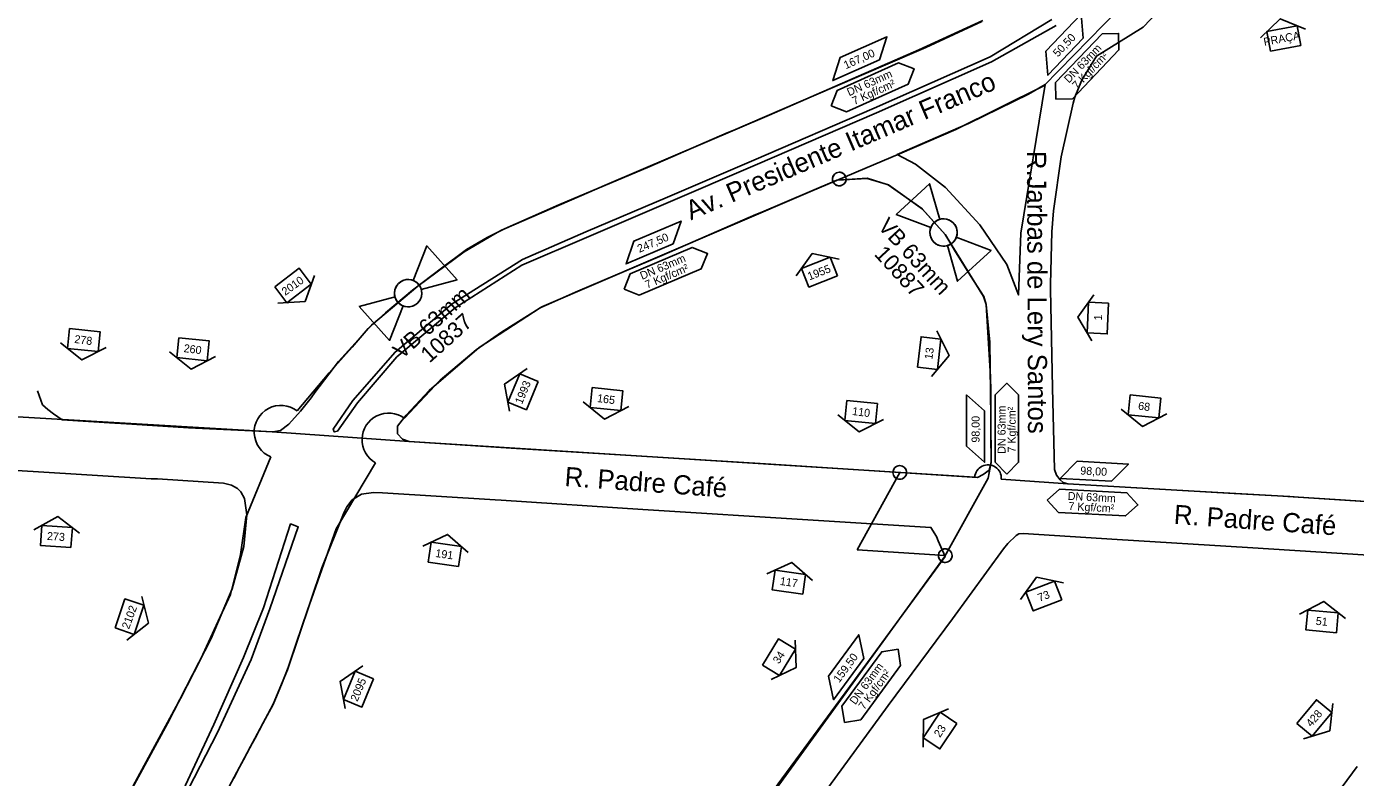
# Model space of a CAD drawing. Extents: x 656692 to 673945, y 7585994 to 7599066.
# Drawn here: x 669220.6 to 669718.8, y 7591557.3 to 7591838.6 of the extents above; entities that cross this region are included whole.
import ezdxf

# ---------------------------------------------------------------- set-up
doc = ezdxf.new("R2010")
doc.units = 0
for name, color, linetype in [('FORMATO', 7, 'Continuous'), ('LOGRADOURO', 7, 'Continuous'), ('LOGRADOURO_TEXTO', 7, 'Continuous'), ('NUM_REF', 7, 'Continuous'), ('SIMBOLO', 7, 'Continuous'), ('TEXTO', 7, 'Continuous'), ('TUBO_PEAD_GN_63', 7, 'Continuous'), ('VALVULA_PEAD_63', 7, 'Continuous')]:
    doc.layers.add(name, color=color, linetype=linetype)

# ---------------------------------------------------------------- blocks, each defined once
blk = doc.blocks.new('INTERLIGACAO_5')
at = {"layer": 'SIMBOLO'}
blk.add_circle((0, 0), 1.28, dxfattribs=at)
for start, end in [(0, 180), (180, 0)]:
    blk.add_arc((0, 0), 1.28, start, end, dxfattribs=at)
blk = doc.blocks.new('VALVULA_PEAD_DN_9')
at = {"layer": 'VALVULA_PEAD_63'}
for points in [[(-1.14, 0.57), (-4.25, 2.13), (-4.25, -2.13), (-1.14, -0.57)], [(-1.14, -0.57), (-4.25, -2.13), (-4.25, 2.13), (-1.14, 0.57)], [(1.14, -0.57), (4.25, -2.13), (4.25, 2.13), (1.14, 0.57)], [(1.14, -0.57), (4.25, -2.13), (4.25, 2.13), (1.14, 0.57)]]:
    blk.add_lwpolyline(points, dxfattribs=at)
blk.add_circle((0, 0), 1.28, dxfattribs=at)
for start, end in [(90, 270), (270, 90), (153.4349, 206.5651), (0, 26.5651), (333.4349, 0)]:
    blk.add_arc((0, 0), 1.28, start, end, dxfattribs=at)
blk = doc.blocks.new('NUM_REF_1')
at = {"layer": 'NUM_REF'}
blk.add_lwpolyline([(-4.3125, 0.9375), (0, 3.75), (4.3125, 0.9375)], dxfattribs=at)
blk.add_lwpolyline([(2.875, -1.875), (2.875, 1.875), (-2.875, 1.875), (-2.875, -1.875)], close=True, dxfattribs=at)

msp = doc.modelspace()

# ---------------------------------------------------------------- linework, layer by layer
at = {"layer": 'LOGRADOURO'}
for p, q in [((669557.74, 7591830.71), (669578.71, 7591840.55)), ((669522.92, 7591815.77), (669555.15, 7591829.59)), ((669555.15, 7591829.59), (669557.74, 7591830.71)), ((669485.55, 7591799.63), (669522.92, 7591815.77)), ((669483.29, 7591798.76), (669485.55, 7591799.63)), ((669454.29, 7591786.15), (669483.29, 7591798.76)), ((669420.18, 7591771.85), (669454.29, 7591786.15)), ((669398.71, 7591762.39), (669420.18, 7591771.85)), ((669384.69, 7591754.23), (669396.19, 7591760.99)), ((669396.19, 7591760.99), (669398.71, 7591762.39)), ((669367.29, 7591741.39), (669384.69, 7591754.23)), ((669349.95, 7591726.69), (669367.29, 7591741.39)), ((669337.5, 7591713.13), (669349.95, 7591726.69)), ((669328.6, 7591701.5), (669337.5, 7591713.13)), ((669224.67, 7591702.13), (669226.6, 7591696.86)), ((669327.32, 7591699.57), (669328.6, 7591701.5)), ((669226.6, 7591696.86), (669228.58, 7591695.12)), ((669228.58, 7591695.12), (669230.71, 7591693.48)), ((669323.29, 7591694.51), (669327.32, 7591699.57)), ((669230.71, 7591693.48), (669233.91, 7591691.22)), ((669233.91, 7591691.22), (669253.68, 7591690.02)), ((669253.68, 7591690.02), (669258, 7591689.71)), ((669258, 7591689.71), (669281.29, 7591688.32)), ((669315.77, 7591687.26), (669318.85, 7591689.69)), ((669318.85, 7591689.69), (669323.29, 7591694.51)), ((669281.29, 7591688.32), (669312.96, 7591686.77)), ((669312.96, 7591686.77), (669315.77, 7591687.26))]:
    msp.add_line(p, q, dxfattribs=at)
for points in [[(669732.22, 7591660.05), (669691.63, 7591662.69), (669689.59, 7591662.76), (669658.39, 7591664.55), (669611.03, 7591667.25), (669609.28, 7591667.76), (669608.08, 7591668.73), (669606.72, 7591670.57), (669605.94, 7591672.66), (669605.3, 7591703.26), (669604.55, 7591740.13), (669604.46, 7591742.15), (669604.98, 7591761.74), (669605.59, 7591769.54), (669608.47, 7591789.79), (669613, 7591809.88), (669613.68, 7591812.11), (669616.11, 7591818.23), (669616.74, 7591819.42), (669621.81, 7591827.55), (669639.28, 7591838.38), (669655.23, 7591855.29)], [(669337.11, 7591687.05), (669335.94, 7591686.75), (669335.53, 7591687.79), (669342.86, 7591698.48), (669358.73, 7591716.65), (669380.11, 7591734.71), (669406.54, 7591751.38), (669430.33, 7591761.73), (669460.86, 7591774.63), (669493.26, 7591788.52), (669538.4, 7591808), (669581.93, 7591827.22), (669604.97, 7591841.22)], [(669606.58, 7591839), (669582.43, 7591825.39), (669539.2, 7591806.27), (669493.71, 7591786.66), (669460.25, 7591772.34), (669431.34, 7591760), (669406.24, 7591749.17), (669381.25, 7591733.18), (669359.46, 7591714.81), (669344.65, 7591697.65), (669337.11, 7591687.05)], [(669547.01, 7591790.73), (669553.9, 7591787.09), (669565.19, 7591778.29), (669578.01, 7591764.38), (669588.19, 7591749.42), (669592.52, 7591738.06), (669593.32, 7591761.21), (669602.48, 7591816.85), (669596.27, 7591813.33), (669573.7, 7591802.28), (669547.01, 7591790.73)], [(669437.06, 7591678.51), (669402.31, 7591680.71), (669364.01, 7591683.16), (669361.5, 7591684.03), (669359.6, 7591686.08), (669359.65, 7591688.85), (669361.37, 7591691.19), (669362.95, 7591692.98), (669371.47, 7591702.22), (669390.3, 7591718.32), (669413.13, 7591733.19), (669415.36, 7591734.21), (669427.32, 7591739.5), (669458.79, 7591752.86), (669494.03, 7591768.15), (669496.29, 7591769.05), (669524.33, 7591781.05), (669535.81, 7591781.75), (669543.63, 7591779.34), (669556.22, 7591770.45), (669564.95, 7591760.73), (669579.43, 7591737.44), (669580.34, 7591734.53), (669581.78, 7591720.39), (669582.18, 7591692.15), (669582.26, 7591675.32), (669581.49, 7591672.43), (669579.2, 7591670.76), (669577.19, 7591669.72), (669497.67, 7591674.79), (669437.06, 7591678.51)], [(669189.53, 7591673.97), (669223.09, 7591671.85), (669267.28, 7591669.21), (669269.69, 7591669.12), (669294.37, 7591667.49), (669297.43, 7591666.85), (669299.71, 7591665.59), (669300.96, 7591664.35), (669302.29, 7591661.82), (669303.15, 7591655.69), (669302.03, 7591643.79), (669297.61, 7591627.93), (669289.8, 7591609.29), (669273.43, 7591577.49), (669247.84, 7591530.44), (669246.69, 7591528.11), (669221.83, 7591481.25), (669219.83, 7591477.69)], [(669487.41, 7591534.49), (669505.53, 7591559.16), (669537.66, 7591602.72), (669564.95, 7591640.08), (669562.43, 7591645.95), (669561.78, 7591647.57), (669559.65, 7591650.99), (669515.56, 7591653.71), (669451.69, 7591657.68), (669398.48, 7591661.15), (669396.27, 7591661.26), (669354.04, 7591663.91), (669350.67, 7591664.04), (669346.21, 7591663.4), (669342.65, 7591661.24), (669340.62, 7591658.69), (669339.71, 7591656.73), (669331.27, 7591635.86), (669318.45, 7591597.66), (669313, 7591584.7), (669288.66, 7591539.12)], [(669237.18, 7591472.91), (669238.3, 7591472.4), (669256.41, 7591505.89), (669276.89, 7591544.54), (669292.15, 7591574.14), (669304.82, 7591601.5), (669311.85, 7591620.43), (669322.45, 7591651.2), (669319.55, 7591652.25), (669309.38, 7591620.83), (669301.89, 7591602.24), (669290.79, 7591577.08), (669275.65, 7591544.75), (669254.37, 7591505.12), (669237.18, 7591472.91)], [(669516.49, 7591547.19), (669543.69, 7591584.23), (669567.75, 7591616.76), (669586.85, 7591643), (669588.45, 7591644.89), (669591.69, 7591647.93), (669592.62, 7591648.55), (669594.2, 7591648.66), (669629.53, 7591646.44), (669678.34, 7591643.5), (669731.61, 7591640.12)], [(669719.43, 7591561.36), (669709.96, 7591548.49)]]:
    msp.add_lwpolyline(points, dxfattribs=at)
at = {"layer": 'SIMBOLO'}
for points in [[(669616.79, 7591834.28), (669603.53, 7591820.37), (669602.79, 7591829.37), (669616.05, 7591843.28)], [(669540.42, 7591826.2), (669522.88, 7591818.36), (669525.6, 7591826.97), (669543.15, 7591834.81)], [(669463.07, 7591757.18), (669445.37, 7591749.69), (669448.26, 7591758.24), (669465.96, 7591765.74)], [(669579.78, 7591694.58), (669579.79, 7591675.36), (669573.04, 7591681.36), (669573.03, 7591700.58)], [(669627.34, 7591668.3), (669608.15, 7591669.33), (669614.5, 7591675.75), (669633.69, 7591674.72)], [(669534.47, 7591601.91), (669523.1, 7591586.42), (669521.21, 7591595.25), (669532.58, 7591610.74)]]:
    msp.add_lwpolyline(points, close=True, dxfattribs=at)
for points in [[(669606.56, 7591811.41), (669606.42, 7591817.6), (669623.84, 7591835.87), (669630.02, 7591836.02), (669630.17, 7591829.83), (669612.75, 7591811.56), (669606.56, 7591811.41)], [(669522.28, 7591808.92), (669524.49, 7591814.7), (669547.55, 7591825), (669553.33, 7591822.79), (669551.12, 7591817.01), (669528.06, 7591806.71), (669522.28, 7591808.92)], [(669444.59, 7591740.26), (669446.92, 7591746), (669470.17, 7591755.85), (669475.9, 7591753.53), (669473.58, 7591747.79), (669450.33, 7591737.94), (669444.59, 7591740.26)], [(669588.16, 7591670.97), (669583.79, 7591675.35), (669583.78, 7591700.6), (669588.16, 7591704.97), (669592.53, 7591700.6), (669592.54, 7591675.35), (669588.16, 7591670.97)], [(669603.31, 7591661.21), (669607.92, 7591665.34), (669633.13, 7591663.98), (669637.26, 7591659.38), (669632.66, 7591655.24), (669607.45, 7591656.6), (669603.31, 7591661.21)], [(669527.25, 7591577.92), (669526.31, 7591584.04), (669541.25, 7591604.4), (669547.37, 7591605.33), (669548.31, 7591599.22), (669533.37, 7591578.86), (669527.25, 7591577.92)]]:
    msp.add_lwpolyline(points, dxfattribs=at)
at = {"layer": 'TUBO_PEAD_GN_63'}
for p, q in [((669531.97, 7591642.51), (669547.97, 7591671.54)), ((669547.97, 7591671.54), (669576.08, 7591669.74)), ((669531.97, 7591642.51), (669565.05, 7591640.39))]:
    msp.add_line(p, q, dxfattribs=at)
for points in [[(669680.71, 7591896.98), (669602.04, 7591816.35), (669569, 7591800.01), (669547.85, 7591790.95), (669514.52, 7591776.78), (669455.36, 7591751.5), (669413.82, 7591733.57), (669398.6, 7591724.07), (669389.2, 7591717.49), (669375.65, 7591706.09), (669362.25, 7591691.88)], [(669579.07, 7591840.83), (669555.17, 7591829.83), (669499.02, 7591805.41), (669438.1, 7591779.5), (669399.53, 7591762.7), (669393.34, 7591759.55), (669385.56, 7591755.06), (669376.19, 7591748.1), (669365.26, 7591739.85), (669355.15, 7591731.31), (669348.71, 7591725.49), (669342.64, 7591718.45), (669334.02, 7591708.87), (669322, 7591694.59)], [(669372.41, 7591378.95), (669440.83, 7591471.78), (669491.4, 7591538.96), (669564.79, 7591639.92), (669581.08, 7591669.47), (669582.24, 7591675.44), (669582.19, 7591685.82), (669582.07, 7591702.02), (669581.98, 7591707.32), (669580.39, 7591734.51), (669579.47, 7591737.43), (669574.48, 7591745.26), (669568.84, 7591754.26), (669565.08, 7591760.62), (669556.55, 7591770.19), (669543.73, 7591779.29), (669535.72, 7591781.72), (669524.61, 7591781.07)], [(669576.08, 7591669.77), (669364.02, 7591683.15), (669312.72, 7591686.76), (669172.51, 7591695.05), (669110.65, 7591698.84), (668958.48, 7591708.51), (668766.36, 7591720.48), (668581.75, 7591731.71)], [(669312.18, 7591677.38), (669302.77, 7591654.72), (669300.81, 7591640.82), (669297.08, 7591625.85), (669291.69, 7591614.21), (669285.88, 7591601.69), (669278.3, 7591586.9), (669263.07, 7591558.77), (669241.51, 7591518.79), (669218.84, 7591476.04), (669140.27, 7591338.73), (669085.61, 7591243.17), (669035.71, 7591157.47), (669005.97, 7591103.03), (668966.34, 7591053.81), (668948.49, 7591034.4), (668935.65, 7591021.83), (668916.48, 7591003.66), (668900.75, 7590989.83), (668884.13, 7590976.88), (668863.91, 7590962.18), (668847.67, 7590951.49)], [(669351.4, 7591675.11), (669336.69, 7591650.41), (669325.94, 7591619.9), (669321.68, 7591607.44), (669318.71, 7591598.47), (669316.12, 7591592.09), (669313.01, 7591584.62), (669309.26, 7591577.72), (669306.25, 7591572.06), (669304.52, 7591568.82), (669303.19, 7591566.31), (669301.87, 7591563.86), (669300.4, 7591561.09), (669298.98, 7591558.45), (669298.25, 7591557.08)], [(669812.04, 7591655.87), (669778.81, 7591657.03), (669774.02, 7591657.34), (669728.51, 7591660.29), (669713.21, 7591661.29), (669697.48, 7591662.3), (669694.18, 7591662.53), (669673.43, 7591663.69), (669610.95, 7591667.27), (669586.06, 7591669.06)]]:
    msp.add_lwpolyline(points, dxfattribs=at)
for centre, radius, start, end in [((669315.92, 7591686.65), 10, 52.5418, 248.0484), ((669356.35, 7591683.8), 10, 53.8708, 240.3237), ((669581.07, 7591669.42), 5, 355.8801, 175.9795)]:
    msp.add_arc(centre, radius, start, end, dxfattribs=at)

# ---------------------------------------------------------------- block references
at = {"layer": 'FORMATO'}
for p, xscale, yscale, rotation in [((669692.01, 7591834.17), 2, 2, 10.671463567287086), ((669517.91, 7591746.58), 1.9999999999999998, 1.9999999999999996, 21.32332355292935), ((669320.49, 7591741.62), 1.9999999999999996, 1.9999999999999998, -142.96985562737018), ((669622.3, 7591729.39), 2.0000000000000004, 1.9999999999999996, 87.44658720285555), ((669242.02, 7591721.15), 1.9999999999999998, 2.0000000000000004, 174.17208706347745), ((669559.02, 7591716.26), 2, 2, -96.63712619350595), ((669283, 7591717.72), 1.9999999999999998, 2.0000000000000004, 174.17208706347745), ((669406.73, 7591701.77), 1.9999999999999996, 1.9999999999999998, 67.45154841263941), ((669438.02, 7591699.02), 1.9999999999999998, 2.0000000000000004, 174.17208706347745), ((669639.73, 7591696.29), 1.9999999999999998, 2.0000000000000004, 174.17208706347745), ((669533.52, 7591694.18), 1.9999999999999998, 2.0000000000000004, 174.17208706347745), ((669231.75, 7591647.55), 1.9999999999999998, 1.9999999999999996, -3.9470478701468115), ((669377.38, 7591640.9), 2, 2, -8.141267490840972), ((669506.42, 7591630.45), 2, 2, -8.141267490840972), ((669602.01, 7591625.29), 1.9999999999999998, 1.9999999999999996, 21.32332355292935), ((669259.18, 7591617.55), 2, 2, -108.78829029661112), ((669706.33, 7591615.76), 2, 2, -5.183900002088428), ((669502.68, 7591602.35), 2, 2, -121.23446205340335), ((669345.03, 7591590.38), 1.9999999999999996, 1.9999999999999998, 67.45154841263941), ((669563.09, 7591574.83), 2.0000000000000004, 2, 56.41810306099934), ((669703.42, 7591579.59), 2, 2, -129.5839750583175)]:
    msp.add_blockref('NUM_REF_1', p, dxfattribs=dict(at, xscale=xscale, yscale=yscale, rotation=rotation))
at = {"layer": 'SIMBOLO', "xscale": 2, "yscale": 2, "rotation": 46.086213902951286}
for p in [(669525.31, 7591781.49), (669547.97, 7591671.54), (669565.05, 7591640.39)]:
    msp.add_blockref('INTERLIGACAO_5', p, dxfattribs=at)
at = {"layer": 'VALVULA_PEAD_63', "xscale": 3.999999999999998}
for p, yscale, rotation in [((669564.42, 7591761.46), 3.999999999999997, -47.41077987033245), ((669363.64, 7591738.72), 3.999999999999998, 41.88338022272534)]:
    msp.add_blockref('VALVULA_PEAD_DN_9', p, dxfattribs=dict(at, yscale=yscale, rotation=rotation))

# ---------------------------------------------------------------- texts
for s, height, rotation, p in [('PRAÇA', 3, 10.6715, (669684.69, 7591831.34)), ('VB 63mm', 6, 312.5892, (669539.46, 7591763.5)), ('10887', 6, 312.5892, (669538.13, 7591753.12)), ('2010', 3, 35.5258, (669317.57, 7591737.69)), ('1955', 3, 21.3233, (669514.11, 7591743.49)), ('VB 63mm', 6, 41.8834, (669361.29, 7591713.78)), ('10837', 6, 41.8834, (669371.65, 7591712.33)), ('1', 3, 87.4466, (669623.78, 7591728.47)), ('278', 3, 352.6678, (669238.36, 7591720.11)), ('260', 3, 352.6678, (669279.34, 7591716.68)), ('13', 3, 81.8586, (669560.18, 7591713.74)), ('1993', 3, 67.4515, (669406.33, 7591696.89)), ('165', 3, 352.6678, (669434.37, 7591697.97)), ('110', 3, 352.6678, (669530.02, 7591693.12)), ('68', 3, 352.6678, (669637.23, 7591695.1)), ('273', 3, 356.053, (669228.16, 7591646.3)), ('191', 3, 351.8587, (669373.71, 7591639.91)), ('117', 3, 351.8587, (669502.9, 7591629.44)), ('73', 3, 21.3233, (669600.38, 7591623.05)), ('2102', 3, 69.7074, (669258.97, 7591612.66)), ('51', 3, 354.8161, (669703.87, 7591614.47)), ('34', 3, 57.2612, (669502.68, 7591599.58)), ('2095', 3, 67.4515, (669344.63, 7591585.5)), ('428', 3, 48.9117, (669702.25, 7591575.97)), ('23', 3, 56.4181, (669563.05, 7591572.06))]:
    msp.add_text(s, height=height, rotation=rotation).set_placement(p)
at = {"layer": 'LOGRADOURO_TEXTO'}
for s, rotation, p in [('Av. Presidente Itamar Franco', 23.2401, (669469.65, 7591765.97)), ('R.Jarbas de Lery Santos', 270.2298, (669595.67, 7591792.01)), ('R. Padre Café', 355.9087, (669422.15, 7591666.49)), ('R. Padre Café', 355.9087, (669650.58, 7591652.32))]:
    msp.add_text(s, height=7.2, rotation=rotation, dxfattribs=at).set_placement(p)
at = {"layer": 'TEXTO'}
for s, rotation, p in [('50,50', 46.3648, (669607.26, 7591826.99)), ('167,00', 24.0693, (669527.77, 7591822.6)), ('DN 63mm', 46.3648, (669611.42, 7591817.24)), ('7 Kgf/cm²', 46.3648, (669614.5, 7591814.95)), ('DN 63mm', 24.0693, (669528.99, 7591812.47)), ('7 Kgf/cm²', 24.0693, (669530.96, 7591809.19)), ('247,50', 22.9614, (669450.35, 7591753.83)), ('DN 63mm', 22.9614, (669451.37, 7591743.68)), ('7 Kgf/cm²', 22.9614, (669453.28, 7591740.36)), ('DN 63mm', 90.0092, (669587.66, 7591678.54)), ('7 Kgf/cm²', 90.0092, (669591.46, 7591679.01)), ('98,00', 90.0092, (669577.91, 7591682.73)), ('98,00', 356.9186, (669615.6, 7591670.81)), ('DN 63mm', 356.9186, (669610.9, 7591661.3)), ('7 Kgf/cm²', 356.9186, (669611.16, 7591657.48)), ('159,50', 53.7289, (669525.26, 7591592.53)), ('DN 63mm', 53.7289, (669531.33, 7591584.32)), ('7 Kgf/cm²', 53.7289, (669534.67, 7591582.45))]:
    msp.add_text(s, height=3, rotation=rotation, dxfattribs=at).set_placement(p)

doc.saveas('drawing.dxf')
